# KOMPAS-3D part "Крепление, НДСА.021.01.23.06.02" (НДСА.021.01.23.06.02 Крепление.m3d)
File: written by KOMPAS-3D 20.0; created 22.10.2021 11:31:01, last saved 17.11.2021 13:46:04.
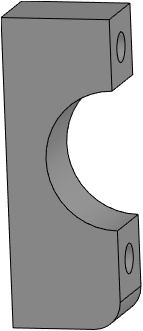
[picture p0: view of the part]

Document properties: Полное имя файла: C:\Users\s.pischagina\Desktop\PLM\НДСА.021.01.23.06.02 Крепление.m3d

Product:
- Part/product: Крепление  | designation НДСА.021.01.23.06.02
    Масса: 0.0881412
    additional columns: <item xmlns="http://appius.ru/pdm" xmlns:xs="http://www.w3.org/2001/XMLSchema" x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; <item xmlns="http://appius.ru/pdm" xmlns:xs="http://www.w3.org/2001/XMLSchema" x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; <item xmlns="http://appius.ru/pdm" xmlns:xs="http://www.w3.org/2001/XMLSchema" x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
    source file: НДСА.021.01.23.06.02 Крепление.cdw

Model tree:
1. Эскиз:1
2. Элемент выдавливания:1
     Расстояние 1 = 14
3. Эскиз:2  (with: Элемент выдавливания:1)
4. Элемент выдавливания:2

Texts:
  НДСА.021.01.23.06.02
